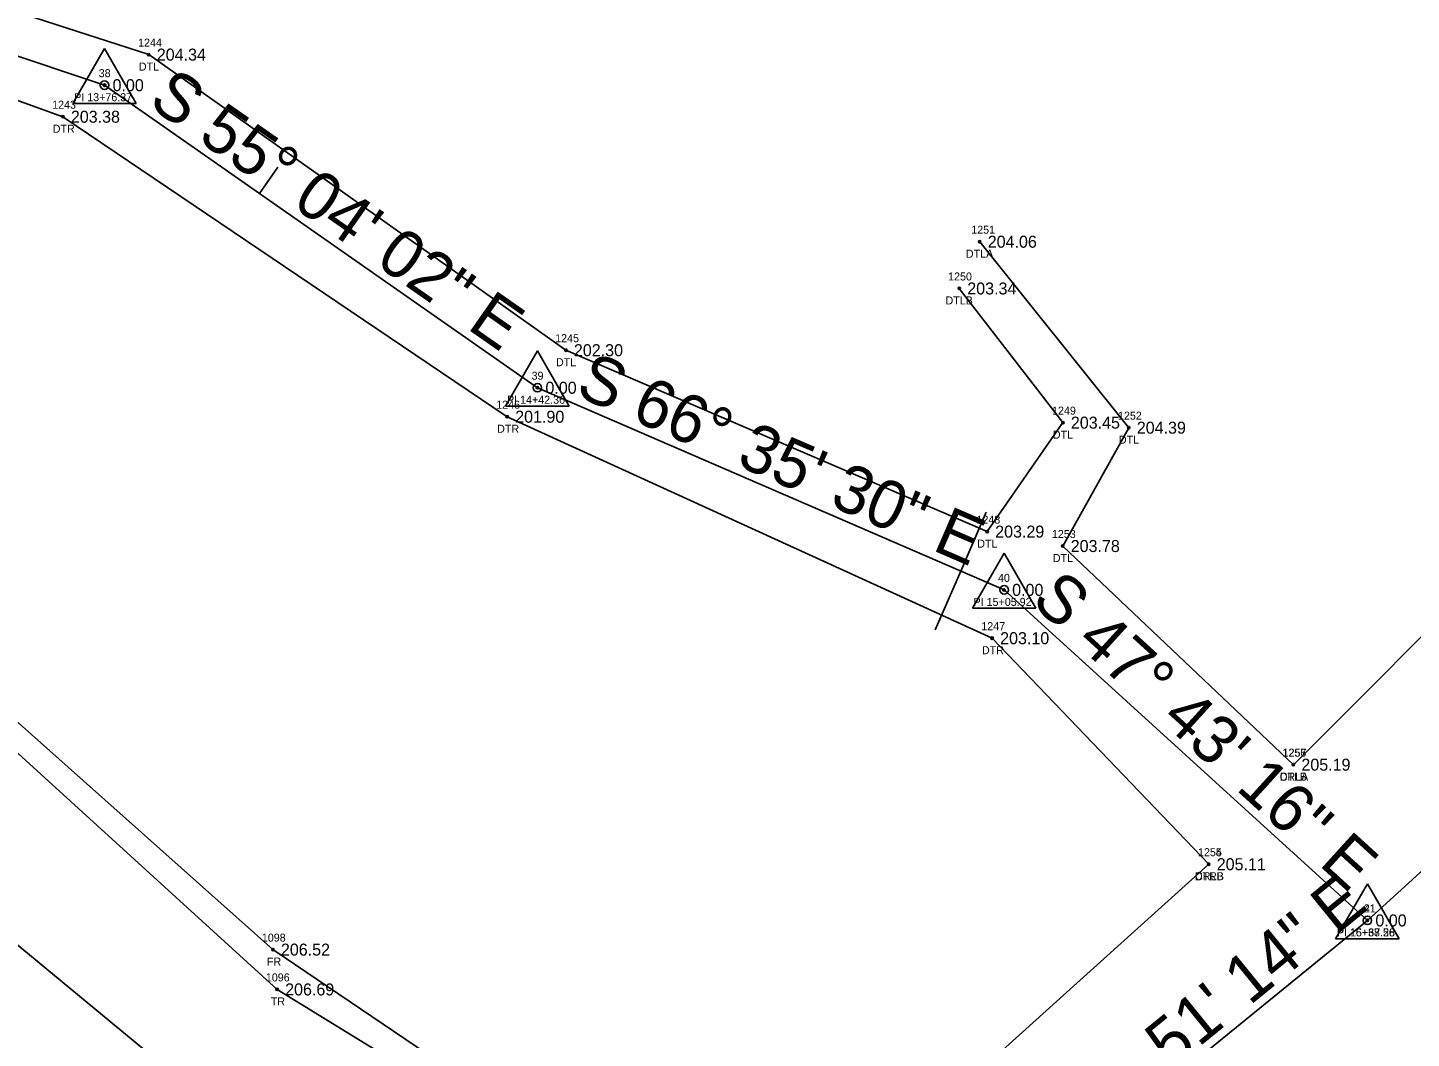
# Model space of a CAD drawing. Extents: x 2259948 to 2261336, y 1064647 to 1065986.
# Drawn here: x 2260727.2 to 2260900.1, y 1065150.5 to 1065276.7 of the extents above; entities that cross this region are included whole.
import ezdxf

# ---------------------------------------------------------------- set-up
doc = ezdxf.new("R2010")
doc.units = 0
for name, color, linetype in [('RD_EX_Fence_Other', 7, 'Continuous'), ('RD_EX_Fence_Other_txCode', 7, 'Continuous'), ('RD_EX_H2O', 7, 'Continuous'), ('RD_EX_H2O_txCode', 7, 'Continuous'), ('RD_EX_Road', 7, 'Continuous'), ('RD_EX_TX_Fence_Other_ELEV', 7, 'Continuous'), ('RD_EX_TX_H2O_ELEV', 7, 'Continuous'), ('RD_EX_TX_VEG_ELEV', 7, 'Continuous'), ('RD_EX_VEG', 7, 'Continuous'), ('RD_EX_VEG_txCode', 7, 'Continuous'), ('RD_HC_Cl', 7, 'Continuous'), ('RD_HC_Data', 7, 'Continuous'), ('RD_HC_Data_Tic', 7, 'Continuous'), ('RD_HC_Survey_ELEV', 7, 'Continuous'), ('RD_HC_txCode', 7, 'Continuous'), ('RD_SMD_Locator', 7, 'Continuous')]:
    doc.layers.add(name, color=color, linetype=linetype)

msp = doc.modelspace()

# ---------------------------------------------------------------- linework, layer by layer
at = {"layer": 'RD_EX_Fence_Other'}
msp.add_lwpolyline([(2260805.94, 1065129.03), (2260757.87, 1065161.54), (2260648.62, 1065258.75)], dxfattribs=at)
at = {"layer": 'RD_EX_H2O'}
for points in [[(2260649.32, 1065303.35), (2260742.36, 1065273.33), (2260794.49, 1065236.41), (2260847.14, 1065213.75), (2260856.6, 1065227.36), (2260843.65, 1065244.12)], [(2260646.56, 1065296.38), (2260731.62, 1065265.57), (2260787.15, 1065228.1), (2260847.76, 1065200.44), (2260874.83, 1065172.21)], [(2260885.41, 1065184.64), (2260936, 1065235.25), (2260958.14, 1065240.42), (2260996.14, 1065264.19), (2261041.44, 1065253.62), (2261057.19, 1065228.35), (2261051.93, 1065209.3), (2261057.29, 1065196.01), (2261078.07, 1065188.45), (2261181.25, 1065188.78), (2261285.07, 1065214.16)], [(2260846.21, 1065249.96), (2260864.84, 1065226.73), (2260856.58, 1065211.95), (2260885.41, 1065184.64)], [(2260789.48, 1065116.29), (2260790.36, 1065118.06), (2260803.42, 1065119.58), (2260845.64, 1065145.91), (2260874.83, 1065172.21)]]:
    msp.add_lwpolyline(points, dxfattribs=at)
at = {"layer": 'RD_EX_Road'}
msp.add_lwpolyline([(2260785.94, 1065112.1), (2260748.83, 1065143.25), (2260679.89, 1065200.15), (2260614.93, 1065253.84), (2260576.4, 1065286.6), (2260541.88, 1065316.4), (2260503.82, 1065350.69)], dxfattribs=at)
at = {"layer": 'RD_EX_VEG'}
msp.add_lwpolyline([(2261134.31, 1064842.95), (2260842.2, 1065097.67), (2260806.91, 1065126.77), (2260758.4, 1065156.57), (2260401.57, 1065481.47), (2260414.95, 1065532.7)], dxfattribs=at)
at = {"layer": 'RD_HC_Cl'}
for p, q in [((2260647.64, 1065299.24), (2260736.83, 1065269.51)), ((2260736.83, 1065269.51), (2260790.93, 1065231.72)), ((2260790.93, 1065231.72), (2260849.26, 1065206.47)), ((2260894.66, 1065165.19), (2260956.6, 1065221.47)), ((2260849.26, 1065206.47), (2260894.66, 1065165.19)), ((2260855.45, 1065133.27), (2260894.66, 1065165.19))]:
    msp.add_line(p, q, dxfattribs=at)
at = {"layer": 'RD_HC_Data'}
for p, q in [((2260732.86, 1065267.21), (2260736.83, 1065274.09)), ((2260736.83, 1065274.09), (2260740.8, 1065267.21)), ((2260732.86, 1065267.21), (2260740.8, 1065267.21)), ((2260786.96, 1065229.43), (2260790.93, 1065236.31)), ((2260790.93, 1065236.31), (2260794.9, 1065229.43)), ((2260786.96, 1065229.43), (2260794.9, 1065229.43)), ((2260845.29, 1065204.17), (2260849.26, 1065211.05)), ((2260849.26, 1065211.05), (2260853.23, 1065204.17)), ((2260845.29, 1065204.17), (2260853.23, 1065204.17)), ((2260890.69, 1065162.89), (2260894.66, 1065169.77)), ((2260890.69, 1065162.89), (2260894.66, 1065169.77)), ((2260894.66, 1065169.77), (2260898.63, 1065162.89)), ((2260894.66, 1065169.77), (2260898.63, 1065162.89)), ((2260890.69, 1065162.89), (2260898.63, 1065162.89)), ((2260890.69, 1065162.89), (2260898.63, 1065162.89))]:
    msp.add_line(p, q, dxfattribs=at)
for centre in [(2260736.83, 1065269.51), (2260790.93, 1065231.72), (2260849.26, 1065206.47), (2260894.66, 1065165.19), (2260894.66, 1065165.19)]:
    msp.add_circle(centre, 0.529, dxfattribs=at)
at = {"layer": 'RD_HC_Data_Tic'}
for p, q in [((2260756.21, 1065255.97), (2260758.5, 1065259.25)), ((2260843.83, 1065208.82), (2260847.01, 1065216.16)), ((2260843.83, 1065208.82), (2260840.65, 1065201.48))]:
    msp.add_line(p, q, dxfattribs=at)
at = {"layer": 'RD_SMD_Locator'}
for centre in [(2260742.36, 1065273.33), (2260736.83, 1065269.51), (2260731.62, 1065265.57), (2260846.21, 1065249.96), (2260843.65, 1065244.12), (2260794.49, 1065236.41), (2260790.93, 1065231.72), (2260787.15, 1065228.1), (2260856.6, 1065227.36), (2260864.84, 1065226.73), (2260847.14, 1065213.75), (2260856.58, 1065211.95), (2260849.26, 1065206.47), (2260847.76, 1065200.44), (2260885.41, 1065184.64), (2260885.41, 1065184.64), (2260874.83, 1065172.21), (2260874.83, 1065172.21), (2260894.66, 1065165.19), (2260894.66, 1065165.19), (2260757.87, 1065161.54), (2260758.4, 1065156.57)]:
    msp.add_circle(centre, 0.15, dxfattribs=at)

# ---------------------------------------------------------------- texts
at = {"layer": 'RD_EX_Fence_Other_txCode'}
for s, p in [('1098', (2260756.49, 1065162.54)), ('FR', (2260757.12, 1065159.54))]:
    msp.add_text(s, height=1, dxfattribs=at).set_placement(p)
at = {"layer": 'RD_EX_H2O_txCode'}
for s, p in [('1244', (2260741.02, 1065274.33)), ('DTL', (2260741.12, 1065271.33)), ('1243', (2260730.28, 1065266.57)), ('DTR', (2260730.35, 1065263.57)), ('1251', (2260845.15, 1065250.96)), ('DTLA', (2260844.48, 1065247.96)), ('1250', (2260842.26, 1065245.12)), ('DTLB', (2260841.93, 1065242.12)), ('1245', (2260793.15, 1065237.41)), ('DTL', (2260793.25, 1065234.41)), ('1246', (2260785.78, 1065229.1)), ('1249', (2260855.25, 1065228.36)), ('1252', (2260863.49, 1065227.73)), ('DTR', (2260785.89, 1065226.1)), ('DTL', (2260855.35, 1065225.36)), ('DTL', (2260863.6, 1065224.73)), ('1248', (2260845.8, 1065214.75)), ('DTL', (2260845.9, 1065211.75)), ('1253', (2260855.23, 1065212.95)), ('DTL', (2260855.34, 1065209.95)), ('1247', (2260846.41, 1065201.44)), ('DTR', (2260846.49, 1065198.44)), ('1256', (2260884.04, 1065185.64)), ('1257', (2260884.07, 1065185.64)), ('CRLA', (2260883.7, 1065182.64)), ('DTLB', (2260883.7, 1065182.64)), ('1254', (2260873.49, 1065173.21)), ('1255', (2260873.49, 1065173.21)), ('CRLB', (2260873.13, 1065170.21)), ('DTRB', (2260873.09, 1065170.21))]:
    msp.add_text(s, height=1, dxfattribs=at).set_placement(p)
at = {"layer": 'RD_EX_TX_Fence_Other_ELEV'}
msp.add_text('206.52', height=1.5, dxfattribs=at).set_placement((2260758.87, 1065160.79))
at = {"layer": 'RD_EX_TX_H2O_ELEV'}
for s, p in [('204.34', (2260743.36, 1065272.58)), ('203.38', (2260732.62, 1065264.82)), ('204.06', (2260847.21, 1065249.21)), ('203.34', (2260844.65, 1065243.37)), ('202.30', (2260795.49, 1065235.66)), ('201.90', (2260788.15, 1065227.35)), ('203.45', (2260857.6, 1065226.61)), ('204.39', (2260865.84, 1065225.98)), ('203.29', (2260848.14, 1065213)), ('203.78', (2260857.58, 1065211.2)), ('203.10', (2260848.76, 1065199.69)), ('205.19', (2260886.41, 1065183.89)), ('205.19', (2260886.41, 1065183.89)), ('205.11', (2260875.83, 1065171.46)), ('205.11', (2260875.83, 1065171.46))]:
    msp.add_text(s, height=1.5, dxfattribs=at).set_placement(p)
at = {"layer": 'RD_EX_TX_VEG_ELEV'}
msp.add_text('206.69', height=1.5, dxfattribs=at).set_placement((2260759.4, 1065155.82))
at = {"layer": 'RD_EX_VEG_txCode'}
for s, p in [('1096', (2260756.99, 1065157.57)), ('TR', (2260757.6, 1065154.57))]:
    msp.add_text(s, height=1, dxfattribs=at).set_placement(p)
at = {"layer": 'RD_HC_Data'}
for s, rotation, p in [('S 55%%d 04\' 02" E', 325.0672, (2260742.12, 1065267.03)), ('S 66%%d 35\' 30" E', 336.5916, (2260795.49, 1065230.83)), ('S 47%%d 43\' 16" E', 317.721, (2260852.48, 1065204.89)), ('N 50%%d 51\' 14" E', 39.146, (2260852.73, 1065132.34))]:
    msp.add_text(s, height=6, rotation=rotation, dxfattribs=at).set_placement(p)
at = {"layer": 'RD_HC_Survey_ELEV'}
for p in [(2260737.83, 1065268.76), (2260791.93, 1065230.97), (2260850.26, 1065205.72), (2260895.66, 1065164.44), (2260895.66, 1065164.44)]:
    msp.add_text('0.00', height=1.5, dxfattribs=at).set_placement(p)
at = {"layer": 'RD_HC_txCode'}
for s, p in [('38', (2260736.1, 1065270.51)), ('PI 13+76.37', (2260733.03, 1065267.51)), ('39', (2260790.2, 1065232.72)), ('PI 14+42.36', (2260787.13, 1065229.72)), ('40', (2260848.49, 1065207.47)), ('PI 15+05.92', (2260845.44, 1065204.47)), ('41', (2260894.21, 1065166.19)), ('21', (2260894.21, 1065166.19)), ('PI 16+38.56', (2260890.83, 1065163.19)), ('PI 15+67.28', (2260890.86, 1065163.19))]:
    msp.add_text(s, height=1, dxfattribs=at).set_placement(p)

doc.saveas('drawing.dxf')
